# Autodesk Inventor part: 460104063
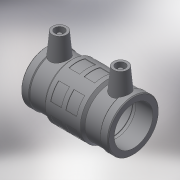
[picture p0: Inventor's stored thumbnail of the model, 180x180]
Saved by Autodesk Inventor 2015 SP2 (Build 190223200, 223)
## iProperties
Created: 2017-06
Part Number: 460104063
Material: Generic
Description: PLASSON LIGHTFIT COUPLER 63
Document SubType Name: Modeling
Designer: KIM
Mass: 89.5427 g
Surface Area: 304.58 cm^2
Volume: 89.5427 cm^3
Density: 1 g/cm^3
Appearance: Default
Author: KIM
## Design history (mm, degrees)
derived "460104.ipt"
feature "Solid1::460104.ipt"
tag "TaggingFeature1"
body "Solid1"
other parameters: "d13" = 118, "d14" = 17.6296, "d15" = 57, "d16" = 57, "d17" = 62.37, "d18" = 63, "d19" = 3.52592, "d20" = 168 deg, "d22" = 72.38, "d23" = 77, "d24" = 70.2086, "d25" = 135 deg, "d26" = 47.2, "d27" = 135 deg, "d29" = 57, "d35" = 15, "d39" = 5 deg, "d44" = 4, "d46" = 14, "d47" = 0, "d52" = 75.46, "d53" = 5.9, "d54" = 5.9, "d55" = 5.9, "d56" = 35 deg, "d58" = 360 deg, "d60" = 11.4, "d61" = 135 deg, "d62" = 47.2, "d63" = 3, "d64" = 0, "d_" = 63, "L_" = 118, "L_1" = 57, "D_" = 77, "A_" = 57, "d_2" = 8
